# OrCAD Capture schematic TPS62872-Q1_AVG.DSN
size D; title: TPS62872-Q1 2.7-V to 6-V Input, 12-A, Stackable, Fast Transient; rev: 1.0; note: Datasheet: SLVSFJ3       EVM: NA; note: Synchronous Step Down Converter; note: Synchronous Step-Down Converters
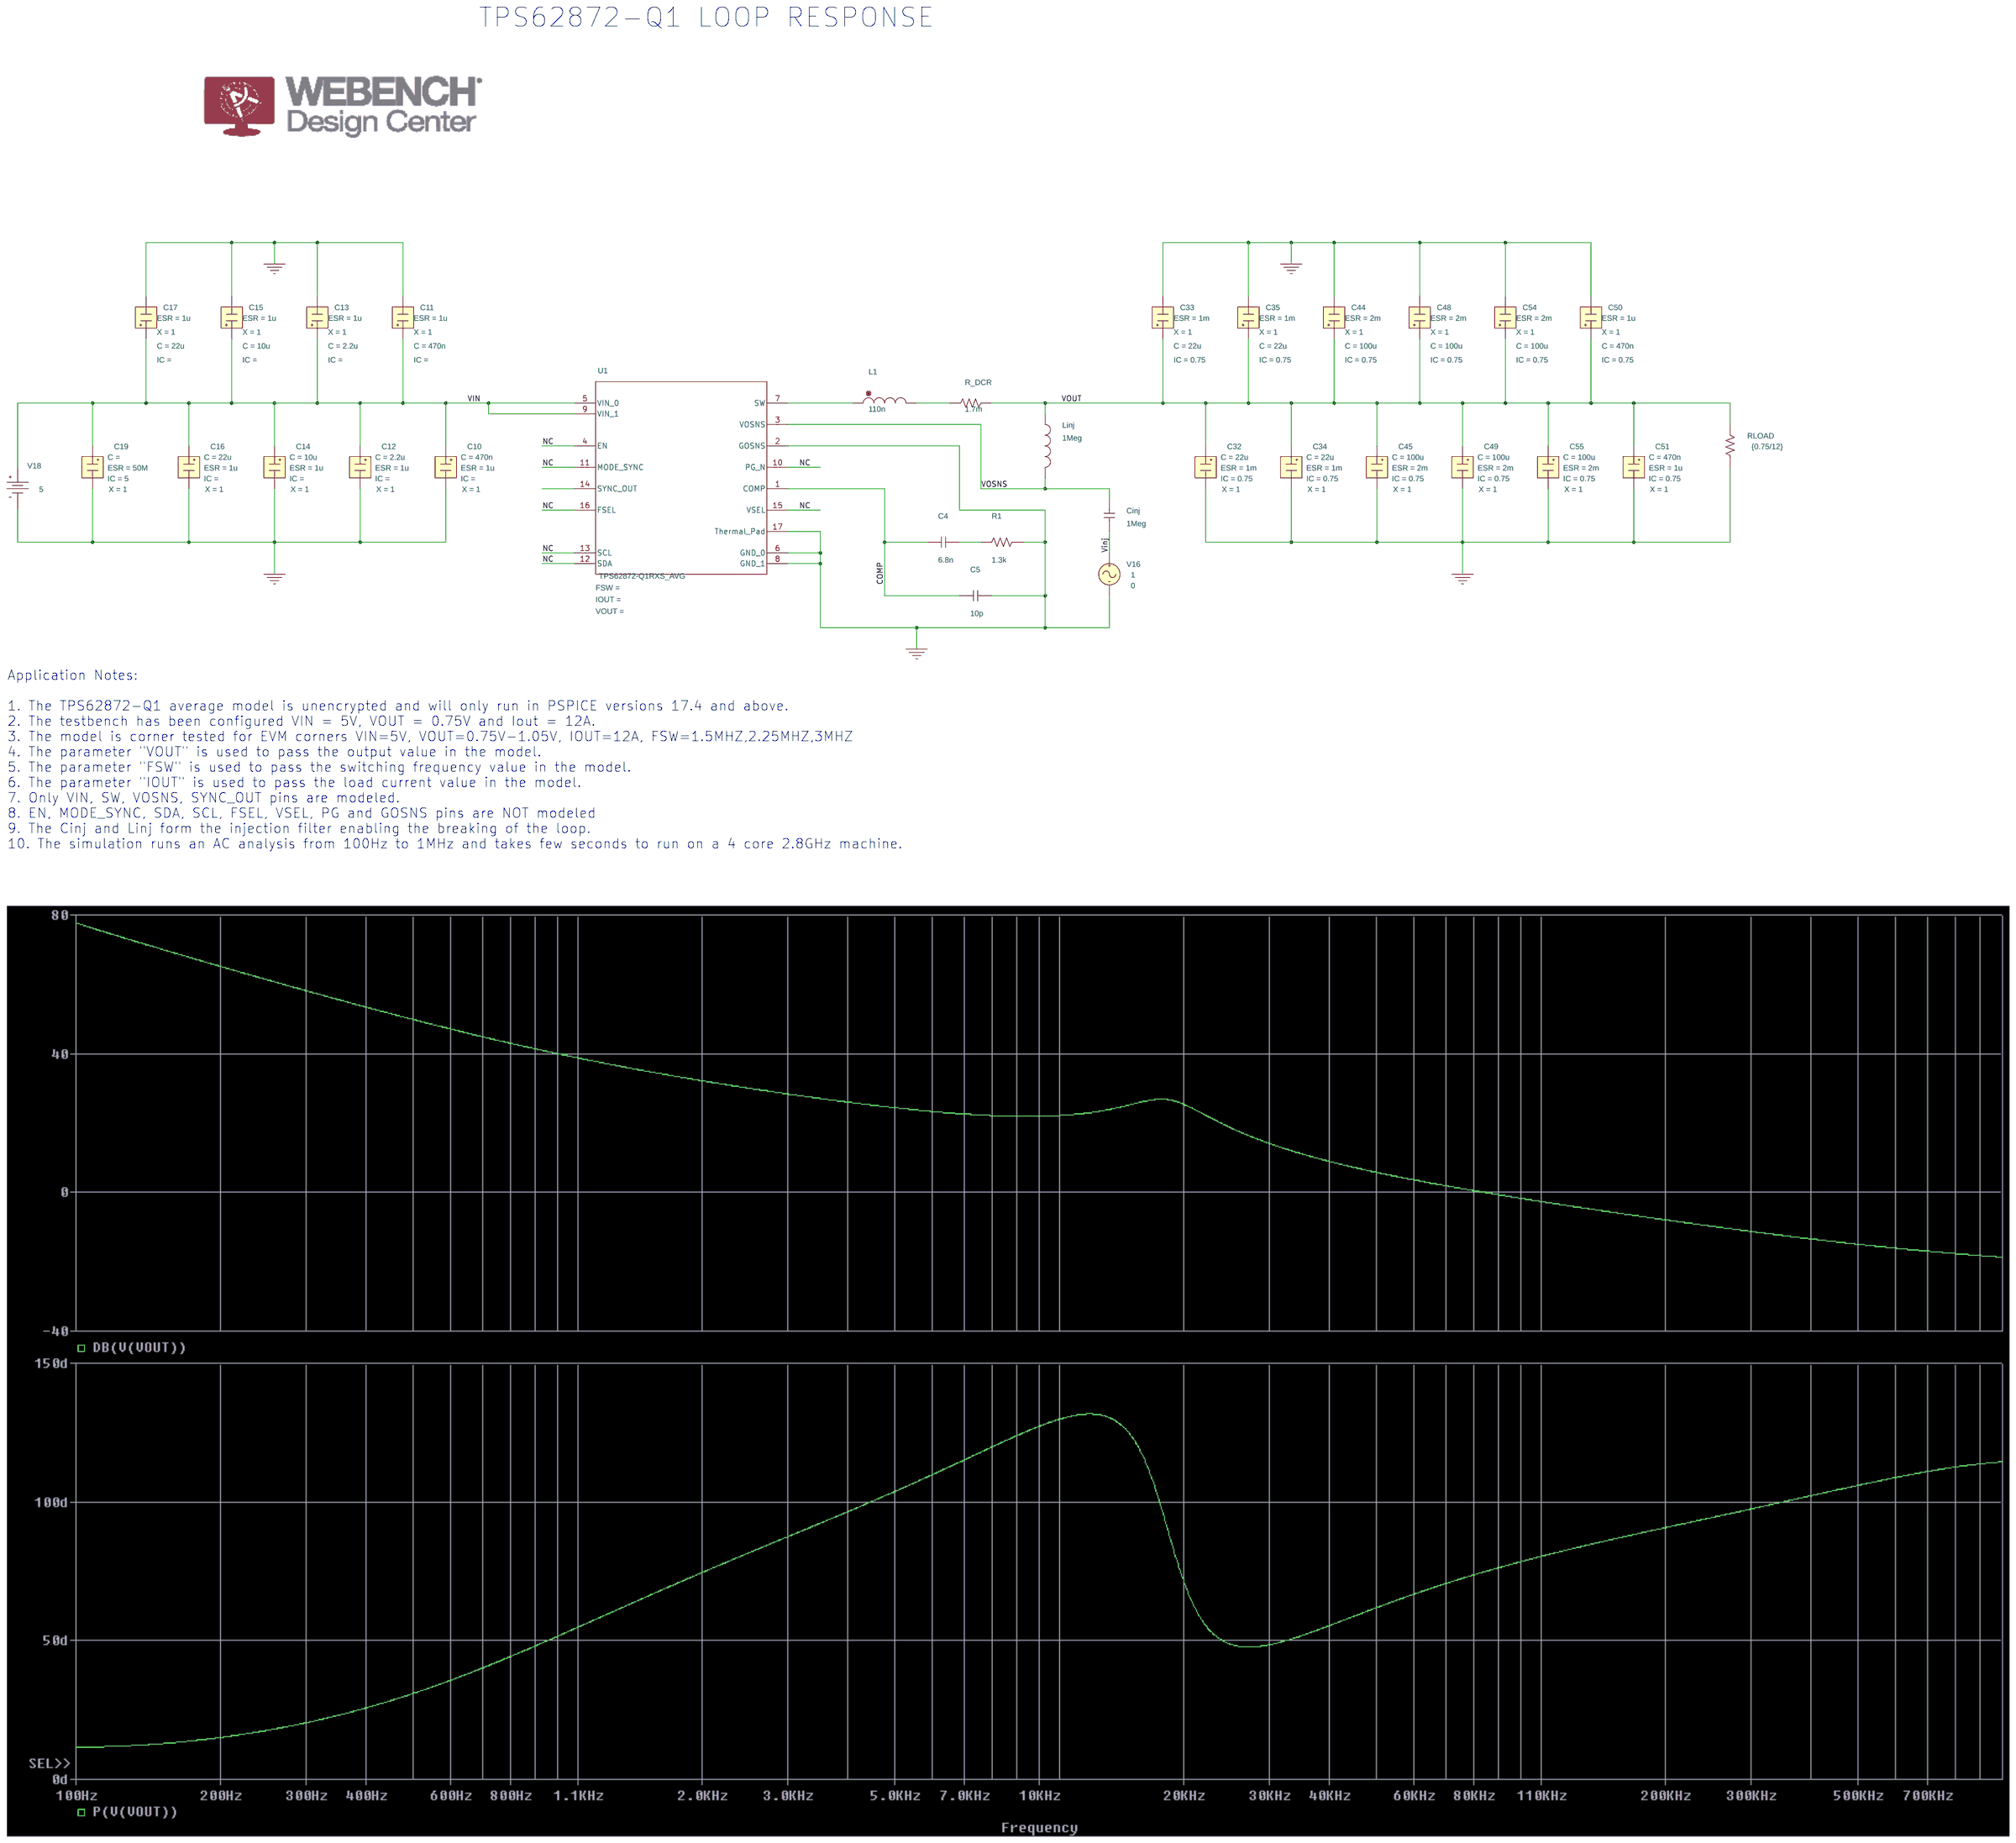
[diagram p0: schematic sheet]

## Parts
C4  6.8n  [cap196]
C5  10p  [cap196]
C10  CESR
C11  CESR
C12  CESR
C13  CESR
C14  CESR
C15  CESR
C16  CESR
C17  CESR
C19  CESR
C32  CESR
C33  CESR
C34  CESR
C35  CESR
C44  CESR
C45  CESR
C48  CESR
C49  CESR
C50  CESR
C51  CESR
C54  CESR
C55  CESR
Cinj  1Meg  [RAD/CK05]
L1  110n  [DISC350x175LS200x100034]
Linj  1Meg  [L2012C]
R1  1.3k  [AXRC05]
R_DCR  1.7m  [AXRC05]
RLOAD  {0.75/12}  [AX/RC05]
U1  TPS62872-Q1RXS_AVG  [RXS0016A-MFG]
V16  VAC
V18  VDC

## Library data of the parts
C4 C5 Cinj = C
C10 C11 = CESR: C: 470n; ESR: 1u; X: 1
C12 C13 = CESR: C: 2.2u; ESR: 1u; X: 1
C14 C15 = CESR: C: 10u; ESR: 1u; X: 1
C16 C17 = CESR: C: 22u; ESR: 1u; X: 1
C19 = CESR: ESR: 50M; IC: 5; X: 1
C32-C35 = CESR: C: 22u; ESR: 1m; IC: 0.75; X: 1
C44 C45 C48 C49 C54 C55 = CESR: C: 100u; ESR: 2m; IC: 0.75; X: 1
C50 C51 = CESR: C: 470n; ESR: 1u; IC: 0.75; X: 1
L1 = L_v2
Linj = L
R1 R_DCR RLOAD = R
U1 = TPS62872-Q1RXS_AVG
V16 = VAC: ACMAG: 1; DC: 0
V18 = VDC: DC: 5

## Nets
VIN: C10.1(IN) C11.1(IN) C12.1(IN) C13.1(IN) C14.1(IN) C15.1(IN) C16.1(IN) C17.1(IN) C19.1(IN) U1.5(VIN_0) U1.9(VIN_1) V18.0(+)
Vinj: Cinj.2 V16.1(+)
0: C5.2 C10.3(OUT) C11.3(OUT) C12.3(OUT) C13.3(OUT) C14.3(OUT) C15.3(OUT) C16.3(OUT) C17.3(OUT) C19.3(OUT) C32.3(OUT) C33.3(OUT) C34.3(OUT) C35.3(OUT) C44.3(OUT) C45.3(OUT) C48.3(OUT) C49.3(OUT) C50.3(OUT) C51.3(OUT) C54.3(OUT) C55.3(OUT) R1.1 RLOAD.1 U1.2(GOSNS) U1.6(GND_0) U1.8(GND_1) U1.17(Thermal_Pad) V16.2(-) V18.1(-)
COMP: C4.1 C5.1 U1.1(COMP)
NC: U1.4(EN) U1.10(PG_N) U1.11(MODE_SYNC) U1.12(SDA) U1.13(SCL) U1.15(VSEL) U1.16(FSEL)
VOSNS: Cinj.1 Linj.2 U1.3(VOSNS)
VOUT: C32.1(IN) C33.1(IN) C34.1(IN) C35.1(IN) C44.1(IN) C45.1(IN) C48.1(IN) C49.1(IN) C50.1(IN) C51.1(IN) C54.1(IN) C55.1(IN) Linj.1 R_DCR.2 RLOAD.2
N16787265: L1.1 U1.7(SW)
N16787268: L1.2 R_DCR.1
N16787666: C4.2 R1.2

Not connected (* = marked no-connect by the designer): U1 14(SYNC_OUT)

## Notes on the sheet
- TPS62872-Q1 LOOP RESPONSE
- Application Notes:
  1. The TPS62872-Q1 average model is unencrypted and will only run in PSPICE versions 17.4 and above.
  2. The testbench has been configured VIN = 5V, VOUT = 0.75V and Iout = 12A.
  3. The model is corner tested for EVM corners VIN=5V, VOUT=0.75V-1.05V, IOUT=12A, FSW=1.5MHZ,2.25MHZ,3MHZ
  4. The parameter "VOUT" is used to pass the output value in the model.
  5. The parameter "FSW" is used to pass the switching frequency value in the model.
  6. The parameter "IOUT" is used to pass the load current value in the model.
  7. Only VIN, SW, VOSNS, SYNC_OUT pins are modeled.
  8. EN, MODE_SYNC, SDA, SCL, FSEL, VSEL, PG and GOSNS pins are NOT modeled
  9. The Cinj and Linj form the injection filter enabling the breaking of the loop.
  10. The simulation runs an AC analysis from 100Hz to 1MHz and takes few seconds to run on a 4 core 2.8GHz machine.
